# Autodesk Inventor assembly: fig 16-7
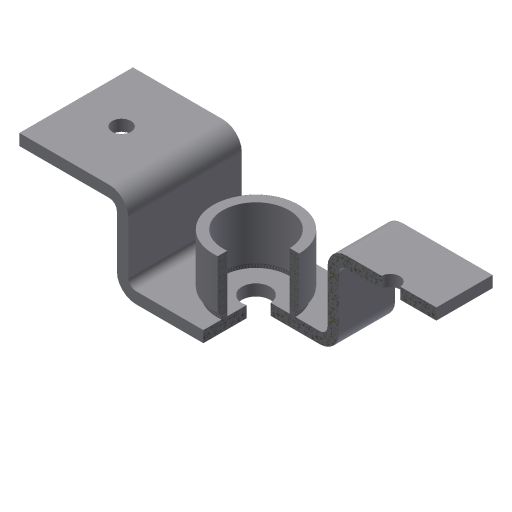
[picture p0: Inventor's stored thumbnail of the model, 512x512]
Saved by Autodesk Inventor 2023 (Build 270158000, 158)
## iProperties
Created: 2005-03
Part Number: fig 16-7
Document SubType Name: Weldment
Designer: CADCIM
Manufacturer: Standard
Standards Organization: Custom
Author: CADCIM
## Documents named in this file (3)
- D:\PROJECTS\Project 2022\Autodesk Inventor For Professional 2023\RESOURCES INVENTOR 2023\RESOURCES INVENTOR 2023\Inventor_2023_Part\Inventor_2023_Part\c16_Inv_2023_prt\fig 16-7\fig 16-7.iam
- D:\PROJECTS\Project 2022\Autodesk Inventor For Professional 2023\RESOURCES INVENTOR 2023\RESOURCES INVENTOR 2023\Inventor_2023_Part\Inventor_2023_Part\c16_Inv_2023_prt\fig 16-7\Bracket.ipt
- D:\PROJECTS\Project 2022\Autodesk Inventor For Professional 2023\RESOURCES INVENTOR 2023\RESOURCES INVENTOR 2023\Inventor_2023_Part\Inventor_2023_Part\c16_Inv_2023_prt\fig 16-7\cylinder.ipt
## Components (2 placed, 2 different names)
1. Bracket:1 — Insert:1
2. cylinder:1 — Insert:1
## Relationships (1: Insert 1)
- Insert:1: Bracket:1 ↔ cylinder:1
